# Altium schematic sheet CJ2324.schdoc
size 127 x 101 mm
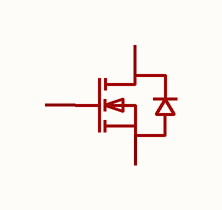
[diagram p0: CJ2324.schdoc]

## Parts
Q?  cj2324  [SOT-23-3_L2.9-W1.6-P1.90-LS2.8-BR]  (value not drawn)

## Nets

Not connected (* = marked no-connect by the designer): Q? 1(G) 2(S) 3(D)

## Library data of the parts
Q? = cj2324: 数量:1个N沟道;漏源电压(Vdss):100V;连续漏极电流(Id):2A;导通电阻(RDS(on)):234mΩ@10V;耗散功率(Pd):-;阈值电压(Vgs(th)):1.2V;; Manufacturer: CJ(江苏长电/长晶); AddInBom: yes; ModelId: 89cb27a44ab2466697082bb9fd73a7d0; ModelName: SOT-23-3L_L2.9-W1.6-H1.1-LS2.8-P0.95; ModelTransform: 114.173,110.236,0,90,0,0,0,0,0; Number: 1个N沟道; Drain to Source Voltage: 100V; Current - Continuous Drain(Id): 2A; Gate Threshold Voltage (Vgs(th)): 1.2V; Gate Charge(Qg): 5.8nC@4.5V; Input Capacitance(Ciss): 190pF; Reverse Transfer Capacitance (Crss@Vds): 13pF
